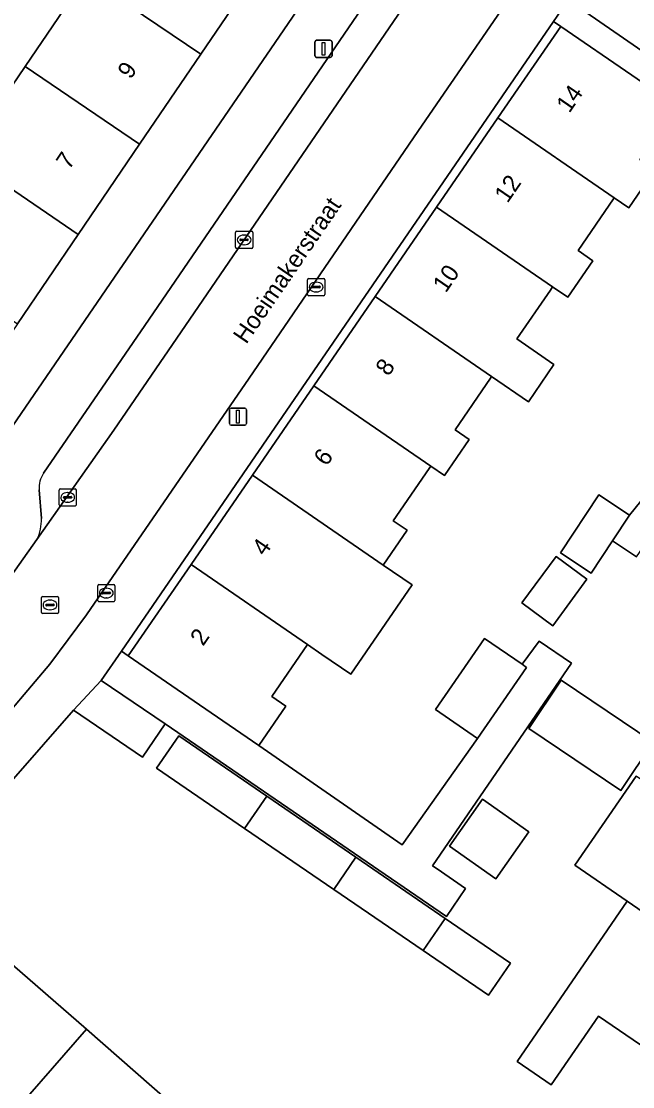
# Model space of a CAD drawing. Extents: x 160023 to 161302, y 384750 to 385707.
# Drawn here: x 160201.5 to 160236.9, y 385239 to 385300.7 of the extents above; entities that cross this region are included whole.
import ezdxf

# ---------------------------------------------------------------- set-up
doc = ezdxf.new("R2010")
doc.units = 0
for name, color, linetype in [('IMGEO_Erf', 7, 'Continuous'), ('IMGEO_Kolk', 7, 'Continuous'), ('IMGEO_Lichtmast', 7, 'Continuous'), ('IMGEO_Muur', 7, 'Continuous'), ('IMGEO_Openbare_ruimte_label', 7, 'Continuous'), ('IMGEO_Pand', 7, 'Continuous'), ('IMGEO_Pand_nummerreeks', 7, 'Continuous'), ('IMGEO_Parkeervlak_open', 7, 'Continuous'), ('IMGEO_Rijbaan_lokaal_open', 7, 'Continuous'), ('IMGEO_Rioolput', 7, 'Continuous'), ('IMGEO_Voetpad_open', 7, 'Continuous')]:
    doc.layers.add(name, color=color, linetype=linetype)

msp = doc.modelspace()

# ---------------------------------------------------------------- linework, layer by layer
at = {"layer": 'IMGEO_Erf'}
for points in [[(160221.619, 385307.412), (160218.975, 385309.223), (160215.422, 385303.999), (160211.901, 385298.822), (160208.353, 385293.604), (160204.806, 385288.388), (160201.287, 385283.214), (160197.683, 385277.915), (160194.049, 385272.571), (160196.571, 385270.843)], [(160221.998, 385284.793), (160225.552, 385289.967), (160229.106, 385295.139), (160232.744, 385300.433), (160232.322, 385300.723), (160207.298, 385264.255), (160207.697, 385263.981), (160211.335, 385269.276), (160214.889, 385274.448), (160218.444, 385279.621)], [(160232.28, 385265.726), (160230.5, 385267.04), (160232.485, 385269.729), (160234.265, 385268.414)], [(160238.103, 385258.985), (160236.224, 385256.188), (160230.893, 385259.769), (160232.772, 385262.566)], [(160226.05, 385248.776), (160229.413, 385246.473), (160229.835, 385246.184), (160228.556, 385244.317), (160224.772, 385246.908), (160219.605, 385250.445), (160214.439, 385253.983), (160209.343, 385257.472), (160210.622, 385259.339), (160215.716, 385255.851), (160220.883, 385252.313)], [(160228.206, 385255.672), (160230.898, 385253.784), (160228.993, 385251.068), (160226.301, 385252.956), (160226.94, 385253.868)]]:
    msp.add_lwpolyline(points, close=True, dxfattribs=at)
for points in [[(160186.466, 385300.778), (160184.874, 385297.615), (160183.158, 385294.204), (160184.707, 385293.425), (160178.329, 385283.256), (160184.707, 385278.922), (160188.342, 385284.267), (160191.051, 385282.425), (160194.656, 385287.725), (160198.174, 385292.898), (160201.722, 385298.115), (160205.269, 385303.332)], [(160238.195, 385292.119), (160236.689, 385289.928), (160235.848, 385290.506), (160235.803, 385290.441), (160233.748, 385287.449), (160234.609, 385286.857), (160233.156, 385284.742), (160232.276, 385285.346), (160232.151, 385285.164), (160230.206, 385282.333), (160232.355, 385280.856), (160230.87, 385278.696), (160228.745, 385280.156), (160228.678, 385280.058), (160226.623, 385277.068), (160227.44, 385276.506), (160226.008, 385274.423), (160225.22, 385274.964), (160225.125, 385274.826), (160223.046, 385271.8), (160223.85, 385271.248), (160222.469, 385269.239), (160224.139, 385268.091), (160220.584, 385262.919), (160218.919, 385264.064), (160218.087, 385264.636), (160216.013, 385261.617), (160216.821, 385261.061), (160215.258, 385258.786), (160223.556, 385253.024), (160227.928, 385259.191), (160225.489, 385260.873), (160228.329, 385264.99), (160230.508, 385263.487), (160231.493, 385264.835), (160233.366, 385263.55), (160225.313, 385251.821), (160225.585, 385251.635), (160227.234, 385250.506), (160226.128, 385248.89), (160209.839, 385260.034), (160208.525, 385258.104), (160204.526, 385260.826), (160195.692, 385250.733)], [(160237.133, 385269.719), (160235.748, 385270.636), (160234.513, 385268.771), (160232.736, 385269.948), (160234.955, 385273.298), (160236.732, 385272.121), (160239.433, 385275.471)], [(160239.734, 385239.828), (160234.941, 385243.119), (160232.201, 385239.128), (160230.223, 385240.486), (160236.597, 385249.768), (160233.569, 385251.847), (160237.12, 385257.017)], [(160200.537, 385246.492), (160205.273, 385242.348), (160210.008, 385238.203)]]:
    msp.add_lwpolyline(points, dxfattribs=at)
at = {"layer": 'IMGEO_Kolk'}
for p, q in [((160213.906, 385287.644), (160213.906, 385288.496)), ((160213.981, 385288.57), (160214.833, 385288.57)), ((160214.165, 385288.064), (160214.165, 385288.076)), ((160214.603, 385288.027), (160214.205, 385288.027)), ((160214.208, 385288.113), (160214.606, 385288.113)), ((160214.394, 385288.35), (160214.419, 385288.35)), ((160214.649, 385288.076), (160214.649, 385288.064)), ((160214.907, 385288.496), (160214.907, 385287.644)), ((160214.833, 385287.57), (160213.981, 385287.57)), ((160214.417, 385287.79), (160214.392, 385287.79)), ((160218.077, 385284.912), (160218.077, 385285.764)), ((160218.152, 385285.838), (160219.004, 385285.838)), ((160218.565, 385285.618), (160218.59, 385285.618)), ((160219.078, 385285.764), (160219.078, 385284.912)), ((160218.336, 385285.332), (160218.336, 385285.344)), ((160218.774, 385285.295), (160218.376, 385285.295)), ((160218.379, 385285.381), (160218.777, 385285.381)), ((160218.588, 385285.058), (160218.563, 385285.058)), ((160218.82, 385285.344), (160218.82, 385285.332)), ((160219.004, 385284.838), (160218.152, 385284.838)), ((160203.69, 385272.73), (160203.69, 385273.582)), ((160203.765, 385273.656), (160204.617, 385273.656)), ((160203.992, 385273.199), (160204.39, 385273.199)), ((160204.178, 385273.436), (160204.203, 385273.436)), ((160204.691, 385273.582), (160204.691, 385272.73)), ((160204.617, 385272.656), (160203.765, 385272.656)), ((160203.949, 385273.15), (160203.949, 385273.162)), ((160204.387, 385273.113), (160203.989, 385273.113)), ((160204.201, 385272.876), (160204.176, 385272.876)), ((160204.433, 385273.162), (160204.433, 385273.15)), ((160205.927, 385267.189), (160205.927, 385268.041)), ((160206.002, 385268.115), (160206.854, 385268.115)), ((160206.186, 385267.609), (160206.186, 385267.621)), ((160206.229, 385267.658), (160206.627, 385267.658)), ((160206.415, 385267.895), (160206.44, 385267.895)), ((160206.67, 385267.621), (160206.67, 385267.609)), ((160206.928, 385268.041), (160206.928, 385267.189)), ((160206.854, 385267.115), (160206.002, 385267.115)), ((160206.624, 385267.572), (160206.226, 385267.572)), ((160206.438, 385267.335), (160206.413, 385267.335))]:
    msp.add_line(p, q, dxfattribs=at)
for points in [[(160213.906, 385287.644), (160213.906, 385288.496)], [(160213.981, 385288.57), (160214.833, 385288.57)], [(160214.907, 385288.496), (160214.907, 385287.644)], [(160214.833, 385287.57), (160213.981, 385287.57)], [(160218.077, 385284.912), (160218.077, 385285.764)], [(160218.152, 385285.838), (160219.004, 385285.838)], [(160219.078, 385285.764), (160219.078, 385284.912)], [(160219.004, 385284.838), (160218.152, 385284.838)], [(160203.69, 385272.73), (160203.69, 385273.582)], [(160203.765, 385273.656), (160204.617, 385273.656)], [(160204.691, 385273.582), (160204.691, 385272.73)], [(160204.617, 385272.656), (160203.765, 385272.656)], [(160205.927, 385267.189), (160205.927, 385268.041)], [(160206.002, 385268.115), (160206.854, 385268.115)], [(160206.928, 385268.041), (160206.928, 385267.189)], [(160206.854, 385267.115), (160206.002, 385267.115)]]:
    msp.add_lwpolyline(points, dxfattribs=at)
for centre, radius, start, end in [((160213.983, 385288.494), 0.0765, 91.55205, 178.44795), ((160213.983, 385288.494), 0.0765, 91.55205, 178.44795), ((160214.205, 385288.073), 0.0403, 85.87752, 175.75265), ((160214.202, 385288.063), 0.0366, 178.93798, 274.71019), ((160214.606, 385288.07), 0.043, 264.86636, 352.45326), ((160214.61, 385288.075), 0.0386, 1.73085, 96.63898), ((160214.831, 385288.494), 0.0765, 1.55205, 88.44795), ((160214.831, 385288.494), 0.0765, 1.55205, 88.44795), ((160213.983, 385287.646), 0.0765, 181.55205, 268.44795), ((160213.983, 385287.646), 0.0765, 181.55205, 268.44795), ((160214.831, 385287.646), 0.0765, 271.55205, 358.44795), ((160214.831, 385287.646), 0.0765, 271.55205, 358.44795), ((160218.154, 385285.762), 0.0765, 91.55205, 178.44795), ((160218.154, 385285.762), 0.0765, 91.55205, 178.44795), ((160219.002, 385285.762), 0.0765, 1.55205, 88.44795), ((160219.002, 385285.762), 0.0765, 1.55205, 88.44795), ((160218.154, 385284.914), 0.0765, 181.55205, 268.44795), ((160218.154, 385284.914), 0.0765, 181.55205, 268.44795), ((160218.376, 385285.341), 0.0403, 85.87752, 175.75265), ((160218.373, 385285.331), 0.0366, 178.93798, 274.71019), ((160218.777, 385285.338), 0.043, 264.86636, 352.45326), ((160218.781, 385285.343), 0.0386, 1.73085, 96.63898), ((160219.002, 385284.914), 0.0765, 271.55205, 358.44795), ((160219.002, 385284.914), 0.0765, 271.55205, 358.44795), ((160203.767, 385273.58), 0.0765, 91.55205, 178.44795), ((160203.767, 385273.58), 0.0765, 91.55205, 178.44795), ((160203.989, 385273.159), 0.0403, 85.87752, 175.75265), ((160204.394, 385273.161), 0.0386, 1.73085, 96.63898), ((160204.615, 385273.58), 0.0765, 1.55205, 88.44795), ((160204.615, 385273.58), 0.0765, 1.55205, 88.44795), ((160203.767, 385272.732), 0.0765, 181.55205, 268.44795), ((160203.767, 385272.732), 0.0765, 181.55205, 268.44795), ((160203.986, 385273.149), 0.0366, 178.93798, 274.71019), ((160204.39, 385273.156), 0.043, 264.86636, 352.45326), ((160204.615, 385272.732), 0.0765, 271.55205, 358.44795), ((160204.615, 385272.732), 0.0765, 271.55205, 358.44795), ((160206.004, 385268.039), 0.0765, 91.55205, 178.44795), ((160206.004, 385268.039), 0.0765, 91.55205, 178.44795), ((160206.226, 385267.618), 0.0403, 85.87752, 175.75265), ((160206.631, 385267.62), 0.0386, 1.73085, 96.63898), ((160206.852, 385268.039), 0.0765, 1.55205, 88.44795), ((160206.852, 385268.039), 0.0765, 1.55205, 88.44795), ((160206.004, 385267.191), 0.0765, 181.55205, 268.44795), ((160206.004, 385267.191), 0.0765, 181.55205, 268.44795), ((160206.223, 385267.608), 0.0366, 178.93798, 274.71019), ((160206.627, 385267.615), 0.043, 264.86636, 352.45326), ((160206.852, 385267.191), 0.0765, 271.55205, 358.44795), ((160206.852, 385267.191), 0.0765, 271.55205, 358.44795)]:
    msp.add_arc(centre, radius, start, end, dxfattribs=at)
for centre, major_axis, ratio, start_param, end_param in [((160214.393, 385288.07), (-0.387, 0.002), 0.722429, 4.712389, 7.853982), ((160214.418, 385288.07), (-0.39, 0.002), 0.717154, 1.570796, 4.712389), ((160218.564, 385285.338), (-0.387, 0.002), 0.722429, 4.712389, 7.853982), ((160218.589, 385285.338), (-0.39, 0.002), 0.717154, 1.570796, 4.712389), ((160204.177, 385273.156), (-0.387, 0.002), 0.722429, 4.712389, 7.853982), ((160204.202, 385273.156), (-0.39, 0.002), 0.717154, 1.570796, 4.712389), ((160206.414, 385267.615), (-0.387, 0.002), 0.722429, 4.712389, 7.853982), ((160206.439, 385267.615), (-0.39, 0.002), 0.717154, 1.570796, 4.712389)]:
    msp.add_ellipse(centre, major_axis=major_axis, ratio=ratio, start_param=start_param, end_param=end_param, dxfattribs=at)
at = {"layer": 'IMGEO_Lichtmast'}
for p, q in [((160218.51, 385298.733), (160218.51, 385299.533)), ((160218.51, 385299.533), (160218.51, 385298.733)), ((160218.61, 385299.633), (160219.4, 385299.633)), ((160219.4, 385299.633), (160218.61, 385299.633)), ((160219.5, 385299.533), (160219.5, 385298.733)), ((160219.5, 385298.733), (160219.5, 385299.533)), ((160219.4, 385298.633), (160218.61, 385298.633)), ((160218.61, 385298.633), (160219.4, 385298.633)), ((160213.554, 385277.43), (160213.554, 385278.23)), ((160213.554, 385278.23), (160213.554, 385277.43)), ((160213.654, 385278.33), (160214.444, 385278.33)), ((160214.444, 385278.33), (160213.654, 385278.33)), ((160214.544, 385278.23), (160214.544, 385277.43)), ((160214.544, 385277.43), (160214.544, 385278.23)), ((160214.444, 385277.33), (160213.654, 385277.33)), ((160213.654, 385277.33), (160214.444, 385277.33))]:
    msp.add_line(p, q, dxfattribs=at)
for points in [[(160218.93, 385299.508), (160219.08, 385299.508), (160219.08, 385298.758), (160218.93, 385298.758), (160218.93, 385299.508)], [(160213.974, 385278.205), (160214.124, 385278.205), (160214.124, 385277.455), (160213.974, 385277.455), (160213.974, 385278.205)]]:
    msp.add_lwpolyline(points, dxfattribs=at)
for centre, start, end in [((160218.61, 385299.533), 90, 180), ((160218.61, 385299.533), 90, 180), ((160219.4, 385299.533), 0, 90), ((160219.4, 385299.533), 360, 90), ((160218.61, 385298.733), 180, 270), ((160218.61, 385298.733), 180, 270), ((160219.4, 385298.733), 270, 0), ((160219.4, 385298.733), 270, 0), ((160213.654, 385278.23), 90, 180), ((160213.654, 385278.23), 90, 180), ((160214.444, 385278.23), 0, 90), ((160214.444, 385278.23), 360, 90), ((160213.654, 385277.43), 180, 270), ((160213.654, 385277.43), 180, 270), ((160214.444, 385277.43), 270, 0), ((160214.444, 385277.43), 270, 0)]:
    msp.add_arc(centre, 0.1, start, end, dxfattribs=at)
at = {"layer": 'IMGEO_Muur'}
msp.add_lwpolyline([(160204.526, 385260.826), (160195.692, 385250.733)], dxfattribs=at)
at = {"layer": 'IMGEO_Pand'}
for points in [[(160215.422, 385303.999), (160208.79, 385308.509), (160208.698, 385308.374), (160205.269, 385303.332), (160211.901, 385298.822)], [(160244.031, 385302.352), (160237.292, 385306.975), (160233.632, 385301.638), (160237.756, 385298.81), (160241.254, 385296.411), (160242.838, 385298.722), (160241.956, 385299.327), (160243.583, 385301.699)], [(160205.269, 385303.332), (160201.722, 385298.115), (160208.353, 385293.604), (160211.901, 385298.822)], [(160239.462, 385295.817), (160236.865, 385297.603), (160232.744, 385300.433), (160229.106, 385295.139), (160235.848, 385290.506), (160236.689, 385289.928), (160238.195, 385292.119), (160237.33, 385292.713)], [(160201.722, 385298.115), (160198.174, 385292.898), (160204.806, 385288.388), (160208.353, 385293.604)], [(160235.803, 385290.441), (160235.848, 385290.506), (160229.106, 385295.139), (160225.552, 385289.967), (160232.276, 385285.346), (160233.156, 385284.742), (160234.609, 385286.857), (160233.748, 385287.449)], [(160201.287, 385283.214), (160204.806, 385288.388), (160198.174, 385292.898), (160194.656, 385287.725)], [(160232.151, 385285.164), (160232.276, 385285.346), (160225.552, 385289.967), (160221.998, 385284.793), (160228.745, 385280.156), (160230.87, 385278.696), (160232.355, 385280.856), (160230.206, 385282.333)], [(160228.678, 385280.058), (160228.745, 385280.156), (160221.998, 385284.793), (160218.444, 385279.621), (160225.22, 385274.964), (160226.008, 385274.423), (160227.44, 385276.506), (160226.623, 385277.068)], [(160225.22, 385274.964), (160218.444, 385279.621), (160214.889, 385274.448), (160222.469, 385269.239), (160223.85, 385271.248), (160223.046, 385271.8), (160225.125, 385274.826)], [(160214.889, 385274.448), (160211.335, 385269.276), (160218.087, 385264.636), (160218.919, 385264.064), (160220.584, 385262.919), (160224.139, 385268.091), (160222.469, 385269.239)], [(160236.732, 385272.121), (160234.955, 385273.298), (160232.736, 385269.948), (160234.513, 385268.771), (160235.748, 385270.636)], [(160230.5, 385267.04), (160232.28, 385265.726), (160234.265, 385268.414), (160232.485, 385269.729)], [(160218.087, 385264.636), (160211.335, 385269.276), (160207.697, 385263.981), (160211.818, 385261.15), (160215.258, 385258.786), (160216.821, 385261.061), (160216.013, 385261.617)], [(160230.768, 385263.307), (160230.508, 385263.487), (160228.329, 385264.99), (160225.489, 385260.873), (160227.928, 385259.191)], [(160204.526, 385260.826), (160208.525, 385258.104), (160209.839, 385260.034), (160206.133, 385262.557)], [(160238.103, 385258.985), (160232.772, 385262.566), (160230.893, 385259.769), (160236.224, 385256.188)], [(160215.716, 385255.851), (160210.622, 385259.339), (160209.343, 385257.472), (160214.439, 385253.983)], [(160246.918, 385250.289), (160240.147, 385254.938), (160237.12, 385257.017), (160233.569, 385251.847), (160236.597, 385249.768), (160243.368, 385245.119), (160246.719, 385250)], [(160220.883, 385252.313), (160215.716, 385255.851), (160214.439, 385253.983), (160219.605, 385250.445)], [(160226.94, 385253.868), (160226.301, 385252.956), (160228.993, 385251.068), (160230.898, 385253.784), (160228.206, 385255.672)], [(160226.05, 385248.776), (160220.883, 385252.313), (160219.605, 385250.445), (160224.772, 385246.908)], [(160236.597, 385249.768), (160230.223, 385240.486), (160232.201, 385239.128), (160234.941, 385243.119), (160239.734, 385239.828), (160243.368, 385245.119)], [(160226.05, 385248.776), (160224.772, 385246.908), (160228.556, 385244.317), (160229.835, 385246.184), (160229.413, 385246.473)], [(160195.147, 385240.332), (160199.882, 385236.187), (160205.273, 385242.348), (160200.537, 385246.492)], [(160199.882, 385236.187), (160204.618, 385232.043), (160210.008, 385238.203), (160205.273, 385242.348)]]:
    msp.add_lwpolyline(points, close=True, dxfattribs=at)
at = {"layer": 'IMGEO_Parkeervlak_open'}
for points in [[(160238.535, 385326.712), (160229.746, 385313.936), (160208.664, 385283.112), (160202.796, 385274.556)], [(160202.405, 385270.714), (160206.863, 385277.053), (160210.266, 385282.015), (160231.347, 385312.838)], [(160202.537, 385273.588), (160202.669, 385271.938)]]:
    msp.add_lwpolyline(points, dxfattribs=at)
for centre, radius, start, end in [((160204.029, 385273.707), 1.497, 145.46359, 184.57782), ((160200.196, 385271.831), 2.475, 333.17626, 2.48082)]:
    msp.add_arc(centre, radius, start, end, dxfattribs=at)
at = {"layer": 'IMGEO_Rijbaan_lokaal_open'}
for points in [[(160244.13, 385331.418), (160241.887, 385328.157), (160231.347, 385312.838), (160210.266, 385282.015), (160206.863, 385277.053), (160202.405, 385270.714), (160200.597, 385268.144), (160197.686, 385264.476), (160185.049, 385250), (160184.219, 385249.049)], [(160224.713, 385294.715), (160236.548, 385311.938), (160240.26, 385317.233), (160246.413, 385326.062), (160248.172, 385328.587)], [(160188.015, 385245.946), (160189.808, 385247.973), (160193.279, 385252.157), (160199.637, 385259.362), (160203.147, 385263.504), (160205.272, 385266.358), (160214.696, 385280.059), (160224.713, 385294.715)]]:
    msp.add_lwpolyline(points, dxfattribs=at)
at = {"layer": 'IMGEO_Rioolput'}
for p, q in [((160202.665, 385266.498), (160202.665, 385267.35)), ((160202.74, 385267.424), (160203.592, 385267.424)), ((160203.153, 385267.204), (160203.178, 385267.204)), ((160203.666, 385267.35), (160203.666, 385266.498)), ((160203.592, 385266.424), (160202.74, 385266.424)), ((160202.924, 385266.918), (160202.924, 385266.93)), ((160203.362, 385266.881), (160202.964, 385266.881)), ((160202.967, 385266.967), (160203.365, 385266.967)), ((160203.176, 385266.644), (160203.151, 385266.644)), ((160203.408, 385266.93), (160203.408, 385266.918))]:
    msp.add_line(p, q, dxfattribs=at)
for points in [[(160202.665, 385266.498), (160202.665, 385267.35)], [(160202.74, 385267.424), (160203.592, 385267.424)], [(160203.666, 385267.35), (160203.666, 385266.498)], [(160203.592, 385266.424), (160202.74, 385266.424)]]:
    msp.add_lwpolyline(points, dxfattribs=at)
for centre, radius, start, end in [((160202.742, 385267.348), 0.0765, 91.55205, 178.44795), ((160202.742, 385267.348), 0.0765, 91.55205, 178.44795), ((160203.59, 385267.348), 0.0765, 1.55205, 88.44795), ((160203.59, 385267.348), 0.0765, 1.55205, 88.44795), ((160202.742, 385266.5), 0.0765, 181.55205, 268.44795), ((160202.742, 385266.5), 0.0765, 181.55205, 268.44795), ((160202.964, 385266.927), 0.0403, 85.87752, 175.75265), ((160202.961, 385266.917), 0.0366, 178.93798, 274.71019), ((160203.365, 385266.924), 0.043, 264.86636, 352.45326), ((160203.369, 385266.929), 0.0386, 1.73085, 96.63898), ((160203.59, 385266.5), 0.0765, 271.55205, 358.44795), ((160203.59, 385266.5), 0.0765, 271.55205, 358.44795)]:
    msp.add_arc(centre, radius, start, end, dxfattribs=at)
for centre, major_axis, ratio, start_param, end_param in [((160203.152, 385266.924), (-0.387, 0.002), 0.722429, 4.712389, 7.853982), ((160203.177, 385266.924), (-0.39, 0.002), 0.717154, 1.570796, 4.712389)]:
    msp.add_ellipse(centre, major_axis=major_axis, ratio=ratio, start_param=start_param, end_param=end_param, dxfattribs=at)
at = {"layer": 'IMGEO_Voetpad_open'}
for points in [[(160241.887, 385328.157), (160244.13, 385331.418), (160236.144, 385332.974), (160232.498, 385327.657), (160231.862, 385328.093), (160230.884, 385326.666), (160231.079, 385326.532), (160233.506, 385324.768), (160222.754, 385309.07), (160221.619, 385307.412), (160196.571, 385270.843), (160195.714, 385269.592), (160194.296, 385267.521), (160186.568, 385258.673), (160181.176, 385252.527), (160180.818, 385252.107)], [(160202.796, 385274.556), (160208.664, 385283.112), (160229.746, 385313.936), (160238.535, 385326.712)], [(160204.526, 385260.826), (160206.133, 385262.557), (160207.298, 385264.255), (160232.322, 385300.723), (160233.168, 385301.956), (160244.96, 385319.14), (160248.653, 385324.526), (160246.413, 385326.062), (160240.26, 385317.233), (160236.548, 385311.938), (160224.713, 385294.715), (160214.696, 385280.059), (160205.272, 385266.358), (160203.147, 385263.504), (160199.637, 385259.362), (160193.279, 385252.157), (160189.808, 385247.973), (160188.015, 385245.946)], [(160202.669, 385271.938), (160202.537, 385273.588)], [(160184.219, 385249.049), (160185.049, 385250), (160197.686, 385264.476), (160200.597, 385268.144), (160202.405, 385270.714)], [(160189.875, 385244.109), (160190.301, 385244.573), (160195.051, 385250), (160195.692, 385250.733), (160204.526, 385260.826)]]:
    msp.add_lwpolyline(points, dxfattribs=at)
for points in [[(160250.884, 385289.663), (160241.254, 385296.411), (160237.756, 385298.81), (160233.632, 385301.638), (160233.168, 385301.956), (160232.322, 385300.723), (160232.744, 385300.433), (160236.865, 385297.603), (160239.462, 385295.817), (160247.078, 385290.78), (160248.855, 385289.603), (160246.635, 385286.253), (160245.191, 385284.034), (160242.971, 385280.684), (160241.652, 385278.821), (160239.433, 385275.471), (160236.732, 385272.121), (160235.748, 385270.636), (160237.133, 385269.719)], [(160211.818, 385261.15), (160207.697, 385263.981), (160207.298, 385264.255), (160206.133, 385262.557), (160209.839, 385260.034), (160226.128, 385248.89), (160227.234, 385250.506), (160225.585, 385251.635), (160225.313, 385251.821), (160233.366, 385263.55), (160231.493, 385264.835), (160230.508, 385263.487), (160230.768, 385263.307), (160227.928, 385259.191), (160223.556, 385253.024), (160215.258, 385258.786)]]:
    msp.add_lwpolyline(points, close=True, dxfattribs=at)
for centre, radius, start, end in [((160204.029, 385273.707), 1.497, 145.46359, 184.57782), ((160200.196, 385271.831), 2.475, 333.17626, 2.48082)]:
    msp.add_arc(centre, radius, start, end, dxfattribs=at)

# ---------------------------------------------------------------- texts
at = {"layer": 'IMGEO_Openbare_ruimte_label'}
msp.add_text('Hoeimakerstraat', height=1, rotation=55.59477, dxfattribs=at).set_placement((160214.533, 385281.987))
at = {"layer": 'IMGEO_Pand_nummerreeks'}
for s, rotation, p in [('9', 55.78148, (160207.834, 385297.323)), ('14', 55.50815, (160233.242, 385295.366)), ('7', 55.78148, (160204.273, 385292.087)), ('12', 55.50815, (160229.662, 385290.156)), ('10', 55.50815, (160226.087, 385284.953)), ('8', 55.50815, (160222.771, 385280.126)), ('6', 55.50815, (160219.189, 385274.915)), ('4', 55.50815, (160215.611, 385269.708)), ('2', 55.50815, (160212.032, 385264.498))]:
    msp.add_text(s, height=1, rotation=rotation, dxfattribs=at).set_placement(p)

doc.saveas('drawing.dxf')
